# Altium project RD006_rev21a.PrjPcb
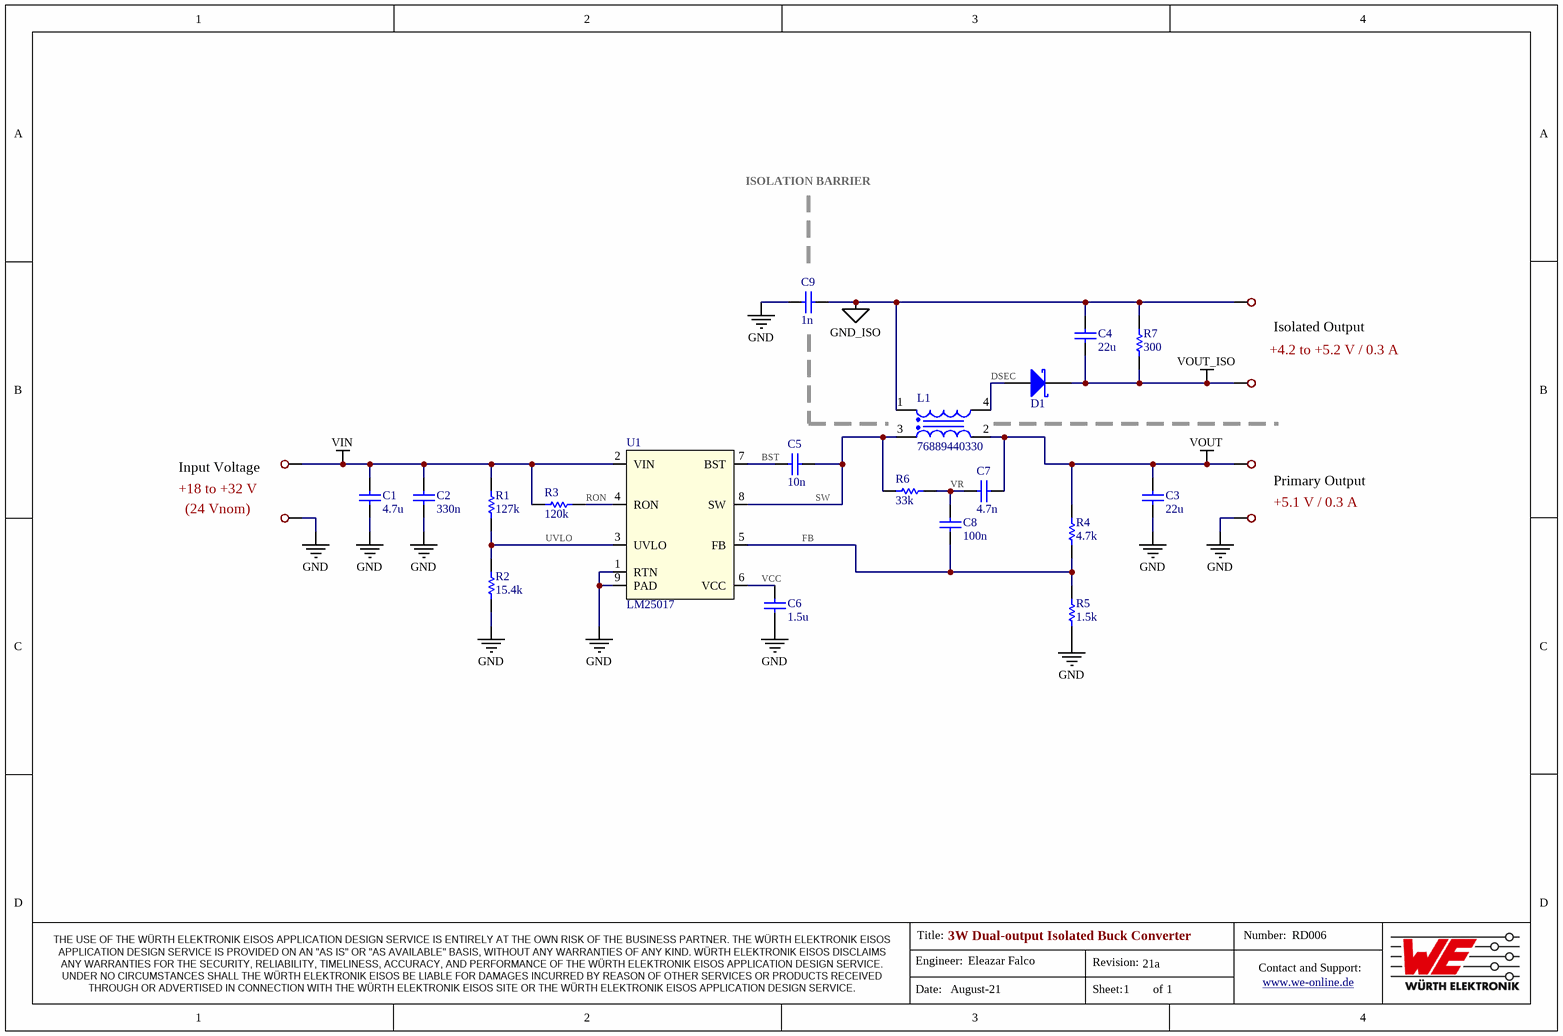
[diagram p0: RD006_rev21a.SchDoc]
1 sheet, 25 parts. Net scope: global (net labels, ports and power ports of the same name join across sheets).
Board file: RD006_rev21a.PcbDoc

## Sheet RD006_rev21a.SchDoc: 3W Dual-output Isolated Buck Converter
size A4; Date: August-21; Author: Eleazar Falco; Engineer: Eleazar Falco; Organization: Wurth Elektronik; RD_Number: RD006; Revision: 21a; SheetNumber: 1; SheetTotal: 1

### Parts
C1  value 4.7u  [C1210]  (hidden comment: 885012209048)
C2  value 330n  [C0603]  (hidden comment: 885012206121)
C3  value 22u  [C1206]  (hidden comment: 885012208019)
C4  value 22u  [C1206]  (hidden comment: 885012208019)
C5  value 10n  [C0603]  (hidden comment: 885012206065)
C6  value 1.5u  [C0805]  (hidden comment: 885012207023)
C7  value 4.7n  [C0603]  (hidden comment: 885012206087)
C8  value 100n  [C0603]  (hidden comment: 885012206095)
C9  value 1n  [C1206]  (hidden comment: 885342208024)
D1  SS1FN6-M3  [D_DO-219AB_(SMF)]  (value not drawn)
J1  Pin_hole_1mm  [J_PIN-TH-ROUND-1MM]  (value not drawn)  (no BOM)
J2  Pin_hole_1mm  [J_PIN-TH-ROUND-1MM]  (value not drawn)  (no BOM)
J3  Pin_hole_1mm  [J_PIN-TH-ROUND-1MM]  (value not drawn)  (no BOM)
J4  Pin_hole_1mm  [J_PIN-TH-ROUND-1MM]  (value not drawn)  (no BOM)
J5  Pin_hole_1mm  [J_PIN-TH-ROUND-1MM]  (value not drawn)  (no BOM)
J6  Pin_hole_1mm  [J_PIN-TH-ROUND-1MM]  (value not drawn)  (no BOM)
L1  76889440330  [WE-TDC HV_8038]
R1  value 127k  [R0603]  (hidden comment: RC0603FR-07127KL)
R2  value 15.4k  [R0603]  (hidden comment: RC0603FR-0715K4L)
R3  value 120k  [R0603]  (hidden comment: RT0603BRD07120KL)
R4  value 4.7k  [R0603]  (hidden comment: RT0603DRE074K7L)
R5  value 1.5k  [R0603]  (hidden comment: RT0603DRD071K5L)
R6  value 33k  [R0603]  (hidden comment: RC0603FR-1033KL)
R7  value 300  [R0805]  (hidden comment: RCS0805300RJNEA)
U1  LM25017  [IC_SOIC-8-DDA0008J]

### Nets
GND: C1.1 C2.1 C3.1 C6.1 C9.1 J2.1 J6.1 R2.1 R5.1 U1.1(RTN) U1.9(PAD)
GND_ISO: C4.2 C9.2 J3.1 L1.1 R7.2
VIN: C1.2 C2.2 J1.1 R1.2 R3.1 U1.2(VIN)
VOUT: C3.2 C7.2 J5.1 L1.2 R4.2
VOUT_ISO: C4.1 D1.C J4.1 R7.1
BST: C5.1 U1.7(BST)
DSEC: D1.A L1.4
FB: C8.1 R4.1 R5.2 U1.5(FB)
RON: R3.2 U1.4(RON)
SW: C5.2 L1.3 R6.1 U1.8(SW)
UVLO: R1.1 R2.2 U1.3(UVLO)
VCC: C6.2 U1.6(VCC)
VR: C7.1 C8.2 R6.2

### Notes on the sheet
- ISOLATION BARRIER
- +4.2 to +5.2 V / 0.3 A
- (near J3) Isolated Output
- (near J1) Input Voltage
- +18 to +32 V
- (24 Vnom)
- Primary Output
- +5.1 V / 0.3 A
- Engineer:
- Title:
- Revision:
- Number:
- Contact and Support:
- www.we-online.de <http://www.we-online.de>
- THE USE OF THE WÜRTH ELEKTRONIK EISOS APPLICATION DESIGN SERVICE IS ENTIRELY AT THE OWN RISK OF THE BUSINESS PARTNER. THE WÜRTH ELEKTRONIK EISOS APPLICATION DESIGN SERVICE IS PROVIDED ON AN "AS IS" OR "AS AVAILABLE" BASIS, WITHOUT ANY WARRANTIES OF ANY KIND. WÜRTH ELEKTRONIK EISOS DISCLAIMS ANY WARRANTIES FOR THE SECURITY, RELIABILITY, TIMELINESS, ACCURACY, AND PERFORMANCE OF THE WÜRTH ELEKTRONIK EISOS APPLICATION DESIGN SERVICE. UNDER NO CIRCUMSTANCES SHALL THE WÜRTH ELEKTRONIK EISOS BE LIABLE FOR DAMAGES INCURRED BY REASON OF OTHER SERVICES OR PRODUCTS RECEIVED THROUGH OR ADVERTISED IN CONNECTION WITH THE WÜRTH ELEKTRONIK EISOS SITE OR THE WÜRTH ELEKTRONIK EISOS APPLICATION DESIGN SERVICE.
- Date:
- Sheet:
- of

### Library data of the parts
C1 = 885012209048: MLCC WCAP-CSGP General Purpose 4.7uF 10% 50V X7R SMD-1210 885012209048; MFR: Wurth Elektronik
C2 = 885012206121: MLCC WCAP-CSGP General Purpose 330nF 10% 50V X7R SMD-0603 885012206121; MFR: Wurth Elektronik
C3 C4 = 885012208019: MLCC WCAP-CSGP General Purpose 22uF 10% 10V X7R SMD-1206 885012208019; MFR: Wurth Elektronik
C5 = 885012206065: MLCC WCAP-CSGP General Purpose 10nF 10% 25V X7R SMD-0603 885012206065; MFR: Wurth Elektronik
C6 = 885012207023: MLCC WCAP-CSGP General Purpose 1.5uF 10% 10V X7R SMD-0805 885012207023; MFR: Wurth Elektronik
C7 = 885012206087: MLCC WCAP-CSGP General Purpose 4.7nF 10% 50V X7R SMD-0603 885012206087; MFR: Wurth Elektronik
C8 = 885012206095: MLCC WCAP-CSGP General Purpose 100nF 10% 50V X7R SMD-0603 885012206095; MFR: Wurth Elektronik
C9 = 885342208024: MLCC WCAP-CSGP HIgh-voltage 1nF 10% 2000V X7R SMD-1206 885342208024; MFR: Wurth Elektronik
D1 = SS1FN6-M3: Schottky Rectifier 1A 60V SMD SMF (DO-219AB) SS1FN6-M3; MFR: Vishay; Type: Schottky Barrier Rectifier
J1-J6 = Pin_hole_1mm: Pin Hole 1mm
L1 = TDC-HV 8038 76889440330: TDC-HV 8038 33uH 1.85A 1:1 SMD Coupled Inductor 76889440330; MFR: Wurth Elektronik
R1 = RC0603FR-07127KL: Thick Film 127k 1% 100mW SMD-0603 RC0603FR-07127KL; MFR: Yageo
R2 = RC0603FR-0715K4L: Thick Film 15.4k 1% 100mW SMD-0603 RC0603FR-0715K4L; MFR: Yageo
R3 = RT0603BRD07120KL: Thin Film 120k 0.1% 100mW SMD-0603 RT0603BRD07120KL; MFR: Yageo
R4 = RT0603DRE074K7L: Thin Film 4.7k 0.1% 100mW SMD-0603 RT0603DRE074K7L; MFR: Yageo
R5 = RT0603DRD071K5L: Thin Film 1.5k 0.1% 100mW SMD-0603 RT0603DRD071K5L; MFR: Yageo
R6 = RC0603FR-1033KL: Thick Film 33k 1% 100mW SMD-0603 RC0603FR-1033KL; MFR: Yageo
R7 = RCS0805300RJNEA: Thick Film 300 5% 400mW SMD-0805 RCS0805300RJNEA; MFR: Yageo
U1 = LM25017: IC Synchronous Buck/Flybuck Controller 48V 0.65A LM25017 SMD SOIC-8 Texas Instruments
